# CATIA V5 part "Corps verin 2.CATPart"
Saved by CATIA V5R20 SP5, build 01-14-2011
Part number: Corps verin 2
Bounding box of the stored display mesh (mm): x -266.089 to -190.001, y -184.999 to -31.576, z -11.133 to 11.133
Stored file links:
  U:\CFAO\Thinkmotion\Corps verin 2.CATPart
  U:\CFAO\Thinkmotion\Bras Articule.CATProduct
  U:\CFAO\Thinkmotion\Squelette Corps verin 2.CATPart
  U:\CFAO\Thinkmotion\Bielle principale.CATPart
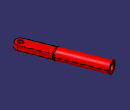
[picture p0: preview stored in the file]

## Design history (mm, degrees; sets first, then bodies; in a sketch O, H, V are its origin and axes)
Set1
  Plane1: linked copy from another document
  Point1: linked copy from another document
  Line1: linked copy from another document
  Point2: linked copy from another document
Body1 (main body)
  Sketch1 on Plane1, origin (0, 0, 0), H (1, 0, 0), V (0, 1, 0)
    line L1 (-190.7152, -171.2861) -> (-212.9987, -115.5775)
    line L2 (-212.9987, -115.5775) -> (-231.5682, -123.0053)
    line L3 (-231.5682, -123.0053) -> (-209.2848, -178.7139)
    arc A1 centre (-200, -175) radius 10 from (-209.2848, -178.7139) to (-190.7152, -171.2861) ccw
    reference projected point E1 (-200, -175) from Point1
    reference projected line E2 (-200, -175) -> (-255.7086, -35.7285) from Line1
    circle A2 centre (-200, -175) radius 5
    reference projected point E3 (-255.7086, -35.7285) from Point2
    angle E2 L3 = 0
    distance L3 L1 = 20
    radius A2 = 5
    distance L2 E3 = 90
    perpendicularity: L2 L1
    tangency: A1 L1, A1 L3
    concentricity: A1 E1, A2 A1
  Pad1: profile Sketch1, direction (0, 0, 1), length 5, mirrored extent
  Sketch2 on face of Pad1 from Sketch1.L2, origin (10.4752, -26.188, 0), H (-0.9285, -0.3714, 0), V (0, 0, 1)
    circle A1 centre (250.6887, 0) radius 11.1803
    point P1 (250.6887, 0)
    reference projected point E1 (250.6887, 0) from Line1
    reference projected point E2 (240.6887, 5) from vertex [face of Pad1 from Sketch1.L2 | end face of Pad1 | face of Pad1 from Sketch1.L1]
    coincidence: P1 H, E2 A1
    concentricity: A1 E1
  Pad2: profile Sketch2, direction (-0.3714, 0.9285, 0), length 90
  Fillet1: radius 5, on edge [start face of Pad1 | start face of Pad2]; edge [face of Pad1 from Sketch1.L3 | start face of Pad2]; edge [start face of Pad2 | end face of Pad1]; edge [start face of Pad2 | face of Pad1 from Sketch1.L1]
  Sketch3 on end face of Pad2, origin (-22.95, 57.375, 0), H (-0.9285, -0.3714, 0), V (0, 0, 1)
    circle A1 centre (250.6887, 0) radius 7
    point P1 (250.6887, 0)
    reference projected point E1 (250.6887, 0) from Point2
    radius A1 = 7
    coincidence: P1 H
    concentricity: A1 E1
  Pocket1: profile Sketch3, direction (0.3714, -0.9285, 0), length 80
